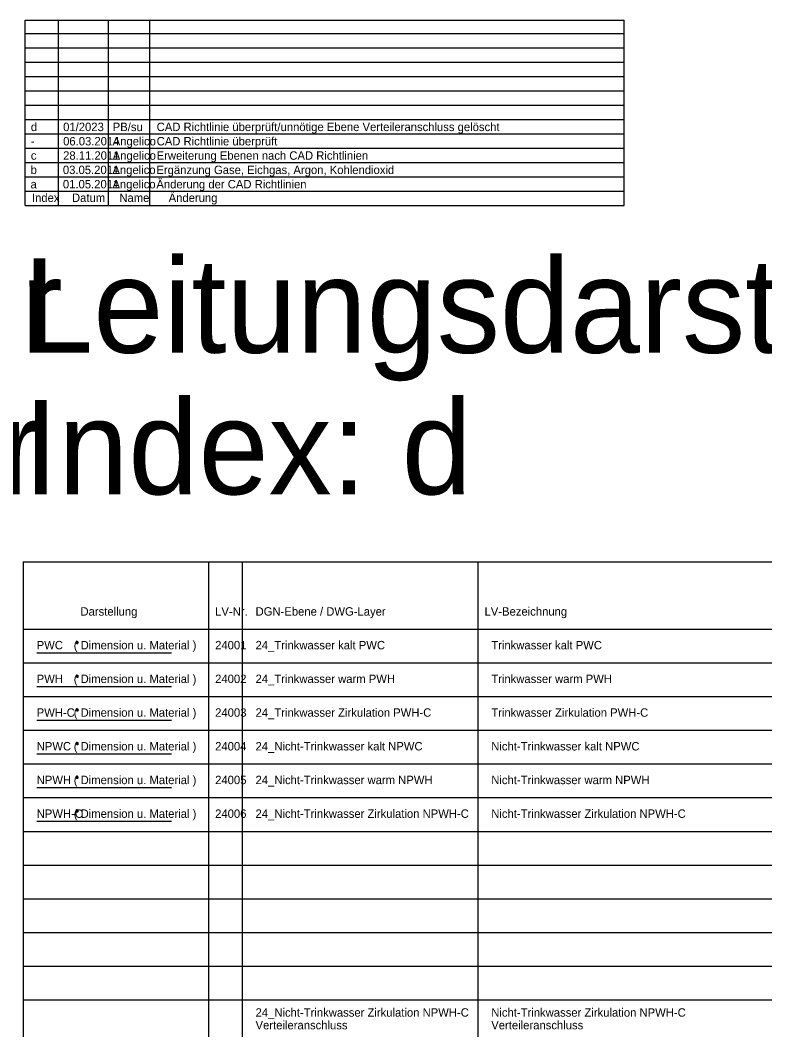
# Model space of a CAD drawing. Extents: x -29 to 48, y -113 to 16.
# Drawn here: x -0.09 to 22.02, y -13.89 to 16.07 of the extents above; entities that cross this region are included whole.
import ezdxf

# ---------------------------------------------------------------- set-up
doc = ezdxf.new("R2010")
doc.units = 0
for name, color, linetype in [('24_Nicht-Trinkwasser kalt NPWC', 7, 'Continuous'), ('24_Nicht-Trinkwasser warm NPWH', 7, 'Continuous'), ('24_Nicht-Trinkwasser Zirkulation NPWH-C', 7, 'Continuous'), ('24_Trinkwasser kalt PWC', 7, 'Continuous'), ('24_Trinkwasser warm PWH', 7, 'Continuous'), ('24_Trinkwasser Zirkulation PWH-C', 7, 'Continuous'), ('Default', 7, 'Continuous')]:
    doc.layers.add(name, color=color, linetype=linetype)

msp = doc.modelspace()

# ---------------------------------------------------------------- linework, layer by layer
at = {"layer": '24_Nicht-Trinkwasser kalt NPWC'}
for p, q in [((1.569, -5.369), (1.631, -5.431)), ((1.631, -5.369), (1.569, -5.431)), ((1.6, -5.356), (1.6, -5.444)), ((1.556, -5.4), (1.644, -5.4)), ((0.4, -5.7), (4.4, -5.7))]:
    msp.add_line(p, q, dxfattribs=at)
at = {"layer": '24_Nicht-Trinkwasser warm NPWH'}
for p, q in [((1.556, -6.4), (1.644, -6.4)), ((1.569, -6.369), (1.631, -6.431)), ((1.631, -6.369), (1.569, -6.431)), ((1.6, -6.356), (1.6, -6.444)), ((0.4, -6.7), (4.4, -6.7))]:
    msp.add_line(p, q, dxfattribs=at)
at = {"layer": '24_Nicht-Trinkwasser Zirkulation NPWH-C'}
for p, q in [((1.556, -7.4), (1.644, -7.4)), ((1.569, -7.369), (1.631, -7.431)), ((1.631, -7.369), (1.569, -7.431)), ((1.6, -7.356), (1.6, -7.444)), ((0.4, -7.7), (4.4, -7.7))]:
    msp.add_line(p, q, dxfattribs=at)
at = {"layer": '24_Trinkwasser kalt PWC'}
for p, q in [((1.569, -2.369), (1.631, -2.431)), ((1.631, -2.369), (1.569, -2.431)), ((1.6, -2.356), (1.6, -2.444)), ((1.556, -2.4), (1.644, -2.4)), ((0.4, -2.7), (4.4, -2.7))]:
    msp.add_line(p, q, dxfattribs=at)
at = {"layer": '24_Trinkwasser warm PWH'}
for p, q in [((1.556, -3.4), (1.644, -3.4)), ((1.569, -3.369), (1.631, -3.431)), ((1.631, -3.369), (1.569, -3.431)), ((1.6, -3.356), (1.6, -3.444)), ((0.4, -3.7), (4.4, -3.7))]:
    msp.add_line(p, q, dxfattribs=at)
at = {"layer": '24_Trinkwasser Zirkulation PWH-C'}
for p, q in [((1.556, -4.4), (1.644, -4.4)), ((1.569, -4.369), (1.631, -4.431)), ((1.631, -4.369), (1.569, -4.431)), ((1.6, -4.356), (1.6, -4.444)), ((0.4, -4.7), (4.4, -4.7))]:
    msp.add_line(p, q, dxfattribs=at)
at = {"layer": 'Default'}
for p, q in [((0.058, 10.57), (0.058, 16.069)), ((0.058, 16.069), (17.846, 16.069)), ((1.046, 10.57), (1.046, 16.069)), ((2.529, 10.57), (2.529, 16.069)), ((3.764, 10.57), (3.764, 16.069)), ((17.846, 10.57), (17.846, 16.069)), ((0.058, 15.67), (17.846, 15.67)), ((0.058, 15.245), (17.846, 15.245)), ((0.058, 14.82), (17.846, 14.82)), ((0.058, 14.395), (17.846, 14.395)), ((0.058, 13.97), (17.846, 13.97)), ((0.058, 13.545), (17.846, 13.545)), ((0.058, 13.12), (17.846, 13.12)), ((0.058, 12.695), (17.846, 12.695)), ((0.058, 12.27), (17.846, 12.27)), ((0.058, 11.845), (17.846, 11.845)), ((0.058, 11.42), (17.846, 11.42)), ((0.058, 10.995), (17.846, 10.995)), ((0.058, 10.57), (17.846, 10.57)), ((0.058, 10.57), (17.846, 10.57)), ((0, 0), (0, -107)), ((0, 0), (32, 0)), ((5.5, 0), (5.5, -107)), ((6.5, 0), (6.5, -107)), ((13.5, 0), (13.5, -107)), ((0, -2), (28.338, -2)), ((0, -2), (32, -2)), ((0, -3), (32, -3)), ((0, -4), (32, -4)), ((0, -5), (32, -5)), ((0, -6), (32, -6)), ((0, -7), (32, -7)), ((0, -8), (32, -8)), ((0, -9), (32, -9)), ((0, -10), (32, -10)), ((0, -11), (32, -11)), ((0, -12), (32, -12)), ((0, -13), (32, -13))]:
    msp.add_line(p, q, dxfattribs=at)

# ---------------------------------------------------------------- texts
at = {"layer": '24_Nicht-Trinkwasser kalt NPWC'}
for s, p in [('NPWC', (0.4, -5.6)), ('( Dimension u. Material )', (1.5, -5.6))]:
    msp.add_text(s, height=0.25, dxfattribs=at).set_placement(p)
at = {"layer": '24_Nicht-Trinkwasser warm NPWH'}
for s, p in [('NPWH', (0.4, -6.6)), ('( Dimension u. Material )', (1.5, -6.6))]:
    msp.add_text(s, height=0.25, dxfattribs=at).set_placement(p)
at = {"layer": '24_Nicht-Trinkwasser Zirkulation NPWH-C'}
for s, p in [('NPWH-C', (0.4, -7.6)), ('( Dimension u. Material )', (1.5, -7.6))]:
    msp.add_text(s, height=0.25, dxfattribs=at).set_placement(p)
at = {"layer": '24_Trinkwasser kalt PWC'}
for s, p in [('PWC', (0.4, -2.6)), ('( Dimension u. Material )', (1.5, -2.6))]:
    msp.add_text(s, height=0.25, dxfattribs=at).set_placement(p)
at = {"layer": '24_Trinkwasser warm PWH'}
for s, p in [('PWH', (0.4, -3.6)), ('( Dimension u. Material )', (1.5, -3.6))]:
    msp.add_text(s, height=0.25, dxfattribs=at).set_placement(p)
at = {"layer": '24_Trinkwasser Zirkulation PWH-C'}
for s, p in [('PWH-C', (0.4, -4.6)), ('( Dimension u. Material )', (1.5, -4.6))]:
    msp.add_text(s, height=0.25, dxfattribs=at).set_placement(p)
at = {"layer": 'Default'}
for s, height, p in [('d     ', 0.25, (0.227, 12.778)), ('01/2023   ', 0.25, (1.185, 12.778)), ('PB/su   ', 0.25, (2.658, 12.778)), ('CAD Richtlinie überprüft/unnötige Ebene Verteileranschluss gelöscht                             ', 0.25, (3.963, 12.778)), ('06.03.2014', 0.25, (1.185, 12.353)), ('Angelico', 0.25, (2.658, 12.353)), ('CAD Richtlinie überprüft                                                                        ', 0.25, (3.963, 12.353)), ('-     ', 0.25, (0.227, 12.353)), ('c     ', 0.25, (0.227, 11.928)), ('28.11.2011', 0.25, (1.185, 11.928)), ('Angelico', 0.25, (2.658, 11.928)), ('Erweiterung Ebenen nach CAD Richtlinien                                                         ', 0.25, (3.963, 11.928)), ('b     ', 0.25, (0.219, 11.503)), ('03.05.2011', 0.25, (1.178, 11.503)), ('Angelico', 0.25, (2.65, 11.503)), ('Ergänzung Gase, Eichgas, Argon, Kohlendioxid                                                    ', 0.25, (3.955, 11.503)), ('a     ', 0.25, (0.219, 11.078)), ('01.05.2011', 0.25, (1.178, 11.078)), ('Angelico', 0.25, (2.65, 11.078)), ('Änderung der CAD Richtlinien                                                                    ', 0.25, (3.955, 11.078)), ('Index', 0.25, (0.259, 10.675)), ('Datum', 0.25, (1.448, 10.675)), ('Name', 0.25, (2.855, 10.675)), ('Änderung', 0.25, (4.319, 10.675)), ('Musterlegende für ', 2.8, (-29, 6.2)), ('Leitungsdarstellung: Sanitär', 2.8, (0, 6.2)), ('Blattpläne Sanitär', 2.8, (-29, 2)), ('Index: d', 2.8, (0, 2)), ('Darstellung', 0.25, (1.7, -1.6)), ('LV-Nr.', 0.25, (5.7, -1.6)), ('DGN-Ebene / DWG-Layer', 0.25, (6.9, -1.6)), ('LV-Bezeichnung', 0.25, (13.7, -1.6)), ('24001', 0.25, (5.7, -2.6)), ('24_Trinkwasser kalt PWC', 0.25, (6.9, -2.6)), ('Trinkwasser kalt PWC', 0.25, (13.9, -2.6)), ('24002', 0.25, (5.7, -3.6)), ('24_Trinkwasser warm PWH', 0.25, (6.9, -3.6)), ('Trinkwasser warm PWH', 0.25, (13.9, -3.6)), ('24003', 0.25, (5.7, -4.6)), ('24_Trinkwasser Zirkulation PWH-C', 0.25, (6.9, -4.6)), ('Trinkwasser Zirkulation PWH-C', 0.25, (13.9, -4.6)), ('24004', 0.25, (5.7, -5.6)), ('24_Nicht-Trinkwasser kalt NPWC', 0.25, (6.9, -5.6)), ('Nicht-Trinkwasser kalt NPWC', 0.25, (13.9, -5.6)), ('24005', 0.25, (5.7, -6.6)), ('24_Nicht-Trinkwasser warm NPWH', 0.25, (6.9, -6.6)), ('Nicht-Trinkwasser warm NPWH', 0.25, (13.9, -6.6)), ('24006', 0.25, (5.7, -7.6)), ('24_Nicht-Trinkwasser Zirkulation NPWH-C', 0.25, (6.9, -7.6)), ('Nicht-Trinkwasser Zirkulation NPWH-C', 0.25, (13.9, -7.6)), ('24_Nicht-Trinkwasser Zirkulation NPWH-C', 0.25, (6.9, -13.5)), ('Nicht-Trinkwasser Zirkulation NPWH-C', 0.25, (13.9, -13.5)), ('Verteileranschluss', 0.25, (6.9, -13.875)), ('Verteileranschluss', 0.25, (13.9, -13.875))]:
    msp.add_text(s, height=height, dxfattribs=at).set_placement(p)

doc.saveas('drawing.dxf')
